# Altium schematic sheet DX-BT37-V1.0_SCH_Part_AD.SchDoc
size A4; SheetNumber: 1; SheetTotal: 1
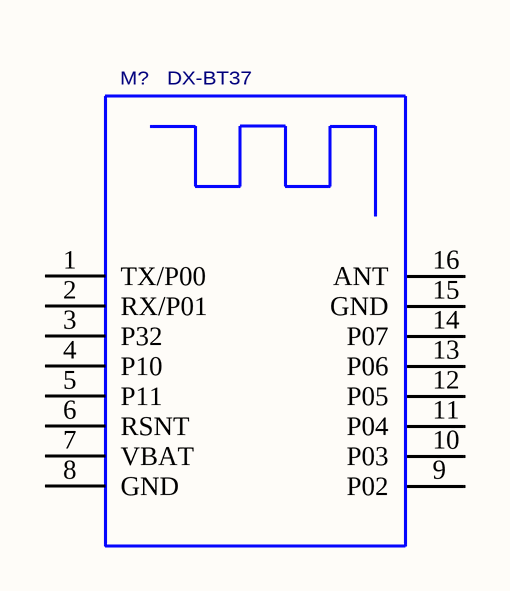
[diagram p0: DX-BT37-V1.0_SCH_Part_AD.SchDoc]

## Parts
M?  DX-BT37

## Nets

Not connected (* = marked no-connect by the designer): M? 1(TX/P00) 2(RX/P01) 3(P32) 4(P10) 5(P11) 6(RSNT) 7(VBAT) 8(GND) 9(P02) 10(P03) 11(P04) 12(P05) 13(P06) 14(P07) 15(GND) 16(ANT)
